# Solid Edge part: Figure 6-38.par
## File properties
Author: CADCIM
Template: Normal.par
Last saved by: Ashutosh-CADCIM
Revision: 7
Application: Solid Edge
Accuracy: 0.99
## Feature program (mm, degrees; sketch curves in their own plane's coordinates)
sketch for "unnamed Protrusion 1" plane through (0, 0, 0) normal (0, -1, 0) x-axis (1, 0, 0)
  line (-50, 0) -> (50, 0)
  line (50, 0) -> (45, 10)
  line (45, 10) -> (-45, 10)
  line (-45, 10) -> (-50, 0)
extrude "unnamed Protrusion 1" add finite 120 symmetric
sketch for "unnamed Cutout 1" plane through (0, 0, 10) normal (0, 0, 1) x-axis (0, 1, 0)
  line (-45, -25) -> (-30, -25)
  arc centre (-30, -30) radius 5 from (-30, -25) to (-30, -35) cw
  line (-45, -35) -> (-30, -35)
  arc centre (-45, -30) radius 5 from (-45, -35) to (-45, -25) cw
extrude "unnamed Cutout 1" cut through along -normal
pattern "unnamed Pattern 1" of "unnamed Cutout 1"
extrude "unnamed Cutout 2" cut through
extrude "unnamed Cutout 3" cut through
extrude "unnamed Cutout 4" cut through
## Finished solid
Body 1: solid body, 22 faces, 60 edges, 40 vertices.
  Faces by surface: plane 14, cylinder 8
  Edges by curve: line 44, circle 16
Bounding box of the edges (mm): 100.000 x 120.000 x 10.000, from (-50, -60, 0) to (50, 60, 10).
Cylindrical faces by radius (mm): R5 x8
Planar faces by outward normal: +x 4, +y 1, +z 1, -x 4, -y 1, -z 1, oblique 2
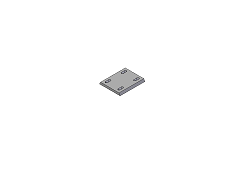
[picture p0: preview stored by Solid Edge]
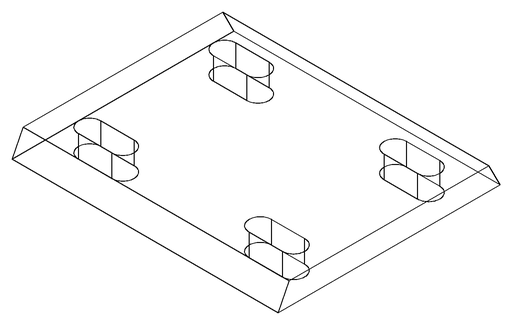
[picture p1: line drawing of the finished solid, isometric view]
